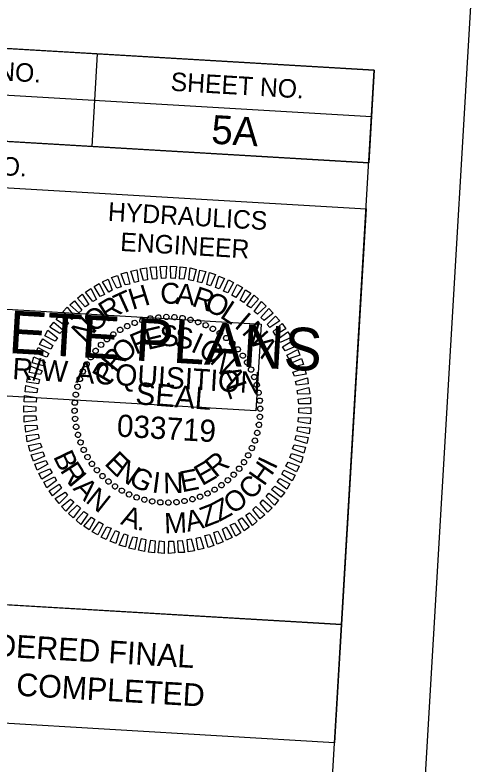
# Model space of a CAD drawing. Extents: x 2012145 to 2014096, y 444445 to 445643.
# Drawn here: x 2013972.6 to 2014096.1, y 445331.9 to 445534.5 of the extents above; entities that cross this region are included whole.
import ezdxf

# ---------------------------------------------------------------- set-up
doc = ezdxf.new("R2010")
doc.units = 0
for name, color, linetype in [('Sheet Data Field CELL', 7, 'Continuous'), ('Sheet Plan And Profile CELL', 7, 'Continuous'), ('Sheet Plot Border Outside CELL', 7, 'Continuous'), ('Sheet Professional Seal CELL', 7, 'Continuous'), ('Sheet Profile Grid Minor CELL', 7, 'Continuous'), ('Sheet Sticker Exception Certification CELL', 7, 'Continuous'), ('Sheet Sticker Incomplete CELL', 7, 'Continuous')]:
    doc.layers.add(name, color=color, linetype=linetype)

msp = doc.modelspace()

# ---------------------------------------------------------------- linework, layer by layer
at = {"layer": 'Sheet Plan And Profile CELL'}
for p, q in [((2013994.8, 445523.97), (2013993.33, 445499.01)), ((2013869.23, 445518.85), (2014068.93, 445507.08)), ((2013868.5, 445506.37), (2014068.2, 445494.6))]:
    msp.add_line(p, q, dxfattribs=at)
for points in [[(2014069.67, 445519.6), (2012572.27, 445607.87), (2012510.48, 444559.69), (2014007.88, 444471.42)], [(2013869.97, 445531.38), (2014069.67, 445519.6), (2014068.2, 445494.6), (2013868.5, 445506.37)], [(2013967.64, 445488), (2014067.46, 445482.12), (2014060.84, 445369.81), (2013961.02, 445375.7)]]:
    msp.add_lwpolyline(points, close=True, dxfattribs=at)
at = {"layer": 'Sheet Plot Border Outside CELL'}
msp.add_lwpolyline([(2012334.32, 444545.03), (2014031.37, 444445), (2014096.1, 445543.09), (2012399.05, 445643.13)], close=True, dxfattribs=at)
at = {"layer": 'Sheet Professional Seal CELL'}
for p, q in [((2014006.98, 445452.04), (2014006.98, 445452.04)), ((2014009.11, 445452.52), (2014009.11, 445452.52)), ((2014011.33, 445452.79), (2014011.33, 445452.79)), ((2014013.49, 445452.96), (2014013.49, 445452.96)), ((2014015.69, 445452.88), (2014015.69, 445452.88)), ((2014017.88, 445452.6), (2014017.88, 445452.6)), ((2014020.01, 445452.13), (2014020.01, 445452.13)), ((2014002.93, 445450.48), (2014002.93, 445450.48)), ((2014004.94, 445451.36), (2014004.94, 445451.36)), ((2014022.08, 445451.55), (2014022.08, 445451.55)), ((2014024.13, 445450.73), (2014024.13, 445450.73)), ((2013999.15, 445448.3), (2013999.15, 445448.3)), ((2014000.97, 445449.44), (2014000.97, 445449.44)), ((2014026.08, 445449.72), (2014026.08, 445449.72)), ((2014027.96, 445448.6), (2014027.96, 445448.6)), ((2013997.41, 445446.9), (2013997.41, 445446.9)), ((2014029.69, 445447.25), (2014029.69, 445447.25)), ((2014031.35, 445445.8), (2014031.35, 445445.8)), ((2013994.37, 445443.77), (2013994.37, 445443.77)), ((2013995.82, 445445.44), (2013995.82, 445445.44)), ((2014032.81, 445444.21), (2014032.81, 445444.21)), ((2013993.02, 445442.05), (2013993.02, 445442.05)), ((2014034.21, 445442.48), (2014034.21, 445442.48)), ((2013991.9, 445440.16), (2013991.9, 445440.16)), ((2014035.36, 445440.65), (2014035.36, 445440.65)), ((2013990.89, 445438.22), (2013990.89, 445438.22)), ((2014036.39, 445438.69), (2014036.39, 445438.69)), ((2013990.07, 445436.16), (2013990.07, 445436.16)), ((2014037.28, 445436.68), (2014037.28, 445436.68)), ((2013989.49, 445434.09), (2013989.49, 445434.09)), ((2014037.96, 445434.64), (2014037.96, 445434.64)), ((2013989.02, 445431.97), (2013989.02, 445431.97)), ((2014038.43, 445432.51), (2014038.43, 445432.51)), ((2013988.74, 445429.78), (2013988.74, 445429.78)), ((2014038.7, 445430.29), (2014038.7, 445430.29)), ((2013988.66, 445427.58), (2013988.66, 445427.58)), ((2014013.77, 445427.85), (2014013.77, 445427.85)), ((2014038.88, 445428.13), (2014038.88, 445428.13)), ((2014038.8, 445425.93), (2014038.8, 445425.93)), ((2013988.83, 445425.42), (2013988.83, 445425.42)), ((2014038.52, 445423.74), (2014038.52, 445423.74)), ((2013989.1, 445423.2), (2013989.1, 445423.2)), ((2014038.04, 445421.61), (2014038.04, 445421.61)), ((2013989.58, 445421.06), (2013989.58, 445421.06)), ((2014037.47, 445419.54), (2014037.47, 445419.54)), ((2013990.26, 445419.02), (2013990.26, 445419.02)), ((2014036.65, 445417.49), (2014036.65, 445417.49)), ((2013991.14, 445417.02), (2013991.14, 445417.02)), ((2014035.63, 445415.54), (2014035.63, 445415.54)), ((2013992.18, 445415.05), (2013992.18, 445415.05)), ((2014034.52, 445413.66), (2014034.52, 445413.66)), ((2013993.32, 445413.23), (2013993.32, 445413.23)), ((2013994.72, 445411.5), (2013994.72, 445411.5)), ((2014033.16, 445411.93), (2014033.16, 445411.93)), ((2013996.18, 445409.91), (2013996.18, 445409.91)), ((2014031.71, 445410.27), (2014031.71, 445410.27)), ((2013997.85, 445408.46), (2013997.85, 445408.46)), ((2014028.39, 445407.41), (2014028.39, 445407.41)), ((2014030.13, 445408.81), (2014030.13, 445408.81)), ((2013999.57, 445407.1), (2013999.57, 445407.1)), ((2014001.46, 445405.99), (2014001.46, 445405.99)), ((2014024.6, 445405.23), (2014024.6, 445405.23)), ((2014026.57, 445406.26), (2014026.57, 445406.26)), ((2014003.4, 445404.97), (2014003.4, 445404.97)), ((2014005.46, 445404.15), (2014005.46, 445404.15)), ((2014007.53, 445403.58), (2014007.53, 445403.58)), ((2014018.42, 445403.19), (2014018.42, 445403.19)), ((2014020.56, 445403.66), (2014020.56, 445403.66)), ((2014022.6, 445404.34), (2014022.6, 445404.34)), ((2014009.65, 445403.1), (2014009.65, 445403.1)), ((2014011.84, 445402.82), (2014011.84, 445402.82)), ((2014014.04, 445402.74), (2014014.04, 445402.74)), ((2014016.2, 445402.92), (2014016.2, 445402.92))]:
    msp.add_line(p, q, dxfattribs=at)
for points in [[(2014007.31, 445462.74), (2014006.45, 445465.95), (2014008.16, 445466.2), (2014008.37, 445462.93)], [(2014009.74, 445463.15), (2014009.13, 445466.39), (2014010.78, 445466.45), (2014010.94, 445463.23)], [(2014012.15, 445463.31), (2014011.79, 445466.54), (2014013.5, 445466.64), (2014013.36, 445463.39)], [(2014014.66, 445463.41), (2014014.6, 445466.67), (2014016.25, 445466.52), (2014015.86, 445463.29)], [(2014017.05, 445463.22), (2014017.25, 445466.47), (2014018.89, 445466.32), (2014018.25, 445463.1)], [(2014019.54, 445462.92), (2014019.93, 445466.16), (2014021.56, 445465.76), (2014020.73, 445462.65)], [(2014000.12, 445460.66), (2013998.69, 445463.55), (2014000.28, 445464.16), (2014001.25, 445461.05)], [(2014002.38, 445461.58), (2014001.26, 445464.55), (2014002.79, 445465.06), (2014003.65, 445461.81)], [(2014004.88, 445462.24), (2014003.9, 445465.3), (2014005.48, 445465.66), (2014005.94, 445462.52)], [(2014021.91, 445462.38), (2014022.55, 445465.55), (2014024.18, 445465.2), (2014023.1, 445462.16)], [(2014024.43, 445461.68), (2014025.12, 445464.9), (2014026.79, 445464.4), (2014025.46, 445461.37)], [(2014026.78, 445460.89), (2014027.72, 445463.94), (2014029.23, 445463.35), (2014027.81, 445460.48)], [(2013995.64, 445458.47), (2013993.94, 445461.13), (2013995.29, 445462), (2013996.77, 445459.01)], [(2013997.91, 445459.59), (2013996.22, 445462.4), (2013997.81, 445463.1), (2013998.89, 445460.13)], [(2014028.98, 445459.86), (2014030.31, 445462.94), (2014031.67, 445462.26), (2014030.11, 445459.45)], [(2013993.65, 445457.09), (2013991.65, 445459.61), (2013993.06, 445460.58), (2013994.64, 445457.68)], [(2014031.17, 445458.78), (2014032.59, 445461.65), (2014034.1, 445460.86), (2014032.23, 445458.17)], [(2014033.4, 445457.5), (2014034.91, 445460.26), (2014036.36, 445459.33), (2014034.31, 445456.84)], [(2013991.57, 445455.66), (2013989.5, 445457.98), (2013990.77, 445459.11), (2013992.55, 445456.3)], [(2014035.26, 445456.04), (2014037.18, 445458.83), (2014038.42, 445457.7), (2014036.33, 445455.37)], [(2013989.82, 445454.01), (2013987.39, 445456.2), (2013988.71, 445457.28), (2013990.66, 445454.76)], [(2014037.22, 445454.42), (2014039.23, 445457.06), (2014040.46, 445455.88), (2014038.13, 445453.66)], [(2013987.96, 445452.21), (2013985.48, 445454.31), (2013986.65, 445455.55), (2013988.71, 445453.07)], [(2014039.03, 445452.76), (2014041.23, 445455.23), (2014042.35, 445453.97), (2014039.93, 445451.95)], [(2013986.35, 445450.41), (2013983.75, 445452.26), (2013984.79, 445453.65), (2013987.05, 445451.32)], [(2014040.72, 445450.91), (2014043.01, 445453.13), (2014044.13, 445451.86), (2014041.42, 445450.06)], [(2013984.73, 445448.5), (2013982.03, 445450.16), (2013983.11, 445451.5), (2013985.58, 445449.35)], [(2014042.36, 445449.01), (2014044.79, 445451.12), (2014045.76, 445449.71), (2014043, 445447.97)], [(2013983.41, 445446.42), (2013980.64, 445447.84), (2013981.48, 445449.34), (2013984.06, 445447.33)], [(2014043.74, 445446.97), (2014046.31, 445448.92), (2014047.18, 445447.42), (2014044.29, 445445.99)], [(2013982.27, 445444.18), (2013979.25, 445445.51), (2013980.09, 445447.02), (2013982.84, 445445.25)], [(2014044.92, 445444.85), (2014047.68, 445446.59), (2014048.54, 445445.04), (2014045.56, 445443.81)], [(2013981.15, 445442.05), (2013978.1, 445443.13), (2013978.84, 445444.64), (2013981.76, 445443.06)], [(2014046.09, 445442.58), (2014048.99, 445444.16), (2014049.55, 445442.57), (2014046.63, 445441.59)], [(2013980.26, 445439.7), (2013977.2, 445440.53), (2013977.65, 445442.15), (2013980.72, 445440.72)], [(2014046.96, 445440.37), (2014049.99, 445441.7), (2014050.55, 445440.06), (2014047.4, 445439.24)], [(2013979.47, 445437.34), (2013976.4, 445437.92), (2013976.84, 445439.6), (2013979.93, 445438.36)], [(2014047.72, 445437.97), (2014050.84, 445439.09), (2014051.3, 445437.51), (2014048.16, 445436.89)], [(2013978.92, 445434.82), (2013975.74, 445435.3), (2013976.04, 445436.99), (2013979.24, 445436)], [(2014048.38, 445435.53), (2014051.64, 445436.49), (2014051.84, 445434.82), (2014048.67, 445434.46)], [(2013978.53, 445432.43), (2013975.29, 445432.73), (2013975.48, 445434.37), (2013978.7, 445433.63)], [(2014048.84, 445433.1), (2014052.04, 445433.86), (2014052.24, 445432.15), (2014049.07, 445432.03)], [(2013978.33, 445429.94), (2013975.08, 445429.98), (2013975.18, 445431.68), (2013978.4, 445431.14)], [(2014049.15, 445430.68), (2014052.43, 445431.18), (2014052.48, 445429.48), (2014049.27, 445429.47)], [(2013978.23, 445427.44), (2013974.96, 445427.24), (2013974.96, 445428.94), (2013978.2, 445428.65)], [(2014049.3, 445428.26), (2014052.57, 445428.47), (2014052.57, 445426.77), (2014049.33, 445427.06)], [(2013978.39, 445425.03), (2013975.1, 445424.52), (2013975.05, 445426.23), (2013978.26, 445426.24)], [(2014049.21, 445425.76), (2014052.46, 445425.72), (2014052.36, 445424.03), (2014049.14, 445424.57)], [(2013978.7, 445422.61), (2013975.5, 445421.84), (2013975.3, 445423.56), (2013978.46, 445423.67)], [(2014049.01, 445423.27), (2014052.25, 445422.98), (2014052.05, 445421.34), (2014048.84, 445422.08)], [(2013979.16, 445420.18), (2013975.89, 445419.22), (2013975.69, 445420.88), (2013978.87, 445421.25)], [(2014048.62, 445420.89), (2014051.8, 445420.4), (2014051.5, 445418.72), (2014048.3, 445419.71)], [(2013979.81, 445417.73), (2013976.69, 445416.62), (2013976.23, 445418.19), (2013979.38, 445418.81)], [(2014048.07, 445418.37), (2014051.14, 445417.79), (2014050.69, 445416.11), (2014047.61, 445417.34)], [(2013980.57, 445415.33), (2013977.54, 445414.01), (2013976.99, 445415.65), (2013980.14, 445416.46)], [(2014047.28, 445416.01), (2014050.34, 445415.18), (2014049.89, 445413.55), (2014046.82, 445414.99)], [(2013981.45, 445413.13), (2013978.55, 445411.55), (2013977.99, 445413.13), (2013980.9, 445414.11)], [(2014046.39, 445413.66), (2014049.43, 445412.58), (2014048.69, 445411.07), (2014045.78, 445412.64)], [(2013982.61, 445410.86), (2013979.86, 445409.12), (2013979, 445410.67), (2013981.97, 445411.9)], [(2014045.26, 445411.52), (2014048.29, 445410.19), (2014047.45, 445408.69), (2014044.7, 445410.45)], [(2013983.79, 445408.73), (2013981.22, 445406.78), (2013980.36, 445408.28), (2013983.25, 445409.72)], [(2014044.13, 445409.28), (2014046.9, 445407.87), (2014046.06, 445406.37), (2014043.47, 445408.37)], [(2013985.17, 445406.7), (2013982.74, 445404.59), (2013981.78, 445406), (2013984.53, 445407.74)], [(2013986.81, 445404.8), (2013984.53, 445402.58), (2013983.4, 445403.85), (2013986.11, 445405.64)], [(2014041.19, 445405.3), (2014043.78, 445403.44), (2014042.75, 445402.05), (2014040.48, 445404.39)], [(2014042.8, 445407.21), (2014045.51, 445405.55), (2014044.43, 445404.21), (2014041.95, 445406.36)], [(2013988.51, 445402.95), (2013986.31, 445400.47), (2013985.18, 445401.74), (2013987.6, 445403.75)], [(2014039.58, 445403.49), (2014042.06, 445401.39), (2014040.88, 445400.16), (2014038.83, 445402.63)], [(2013990.31, 445401.29), (2013988.31, 445398.65), (2013987.07, 445399.83), (2013989.41, 445402.04)], [(2014037.72, 445401.7), (2014040.14, 445399.5), (2014038.83, 445398.43), (2014036.87, 445400.95)], [(2013992.27, 445399.67), (2013990.35, 445396.88), (2013989.12, 445398), (2013991.21, 445400.33)], [(2014035.97, 445400.05), (2014038.04, 445397.72), (2014036.77, 445396.6), (2014034.98, 445399.41)], [(2013994.14, 445398.21), (2013992.62, 445395.44), (2013991.18, 445396.38), (2013993.23, 445398.86)], [(2013996.37, 445396.92), (2013994.95, 445394.05), (2013993.44, 445394.84), (2013995.3, 445397.54)], [(2014031.9, 445397.23), (2014033.59, 445394.58), (2014032.24, 445393.71), (2014030.76, 445396.7)], [(2014033.88, 445398.62), (2014035.89, 445396.1), (2014034.48, 445395.13), (2014032.9, 445398.03)], [(2013998.56, 445395.84), (2013997.22, 445392.77), (2013995.86, 445393.45), (2013997.43, 445396.26)], [(2014000.75, 445394.81), (2013999.82, 445391.76), (2013998.3, 445392.35), (2013999.72, 445395.22)], [(2014029.63, 445396.11), (2014031.32, 445393.31), (2014029.72, 445392.6), (2014028.64, 445395.57)], [(2014003.11, 445394.02), (2014002.42, 445390.81), (2014000.74, 445391.31), (2014002.07, 445394.33)], [(2014005.62, 445393.32), (2014004.98, 445390.15), (2014003.35, 445390.5), (2014004.43, 445393.54)], [(2014007.99, 445392.78), (2014007.6, 445389.55), (2014005.97, 445389.95), (2014006.81, 445393.05)], [(2014022.66, 445393.47), (2014023.63, 445390.41), (2014022.06, 445390.05), (2014021.59, 445393.18)], [(2014025.15, 445394.12), (2014026.28, 445391.15), (2014024.75, 445390.64), (2014023.89, 445393.9)], [(2014027.41, 445395.04), (2014028.84, 445392.15), (2014027.25, 445391.55), (2014026.29, 445394.66)], [(2014010.48, 445392.48), (2014010.29, 445389.24), (2014008.65, 445389.39), (2014009.29, 445392.61)], [(2014012.87, 445392.29), (2014012.93, 445389.03), (2014011.29, 445389.18), (2014011.68, 445392.41)], [(2014015.38, 445392.4), (2014015.74, 445389.17), (2014014.04, 445389.07), (2014014.18, 445392.32)], [(2014017.8, 445392.55), (2014018.41, 445389.31), (2014016.75, 445389.26), (2014016.59, 445392.48)], [(2014020.23, 445392.96), (2014021.09, 445389.76), (2014019.37, 445389.51), (2014019.16, 445392.77)]]:
    msp.add_lwpolyline(points, close=True, dxfattribs=at)
for centre, major_axis in [((2014004.93, 445451.33), (-0.254, 0.674)), ((2014007.01, 445452.01), (-0.194, 0.693)), ((2014009.14, 445452.5), (-0.133, 0.708)), ((2014011.31, 445452.81), (-0.071, 0.717)), ((2014013.49, 445452.93), (-0.008, 0.72)), ((2014015.68, 445452.86), (0.055, 0.718)), ((2014017.85, 445452.6), (0.117, 0.71)), ((2014019.99, 445452.15), (0.179, 0.697)), ((2014022.09, 445451.51), (0.239, 0.679)), ((2014000.99, 445449.43), (-0.367, 0.62)), ((2014002.92, 445450.47), (-0.311, 0.649)), ((2014024.12, 445450.7), (0.297, 0.656)), ((2014026.07, 445449.71), (0.353, 0.627)), ((2013999.16, 445448.24), (-0.419, 0.585)), ((2014027.93, 445448.55), (0.407, 0.594)), ((2014029.68, 445447.24), (0.457, 0.557)), ((2013995.84, 445445.39), (-0.515, 0.504)), ((2013997.44, 445446.89), (-0.469, 0.546)), ((2014031.31, 445445.78), (0.504, 0.515)), ((2013994.38, 445443.76), (-0.557, 0.457)), ((2014032.8, 445444.18), (0.546, 0.469)), ((2013993.07, 445442.01), (-0.594, 0.407)), ((2014034.15, 445442.46), (0.585, 0.419)), ((2013991.91, 445440.15), (-0.627, 0.353)), ((2014035.35, 445440.63), (0.62, 0.367)), ((2013990.92, 445438.2), (-0.656, 0.297)), ((2014036.38, 445438.7), (0.649, 0.311)), ((2013990.11, 445436.17), (-0.679, 0.239)), ((2014037.24, 445436.69), (0.674, 0.254)), ((2013989.47, 445434.08), (-0.697, 0.179)), ((2014037.92, 445434.61), (0.693, 0.194)), ((2013989.02, 445431.94), (-0.71, 0.117)), ((2014038.42, 445432.48), (0.708, 0.133)), ((2013988.76, 445429.77), (-0.718, 0.055)), ((2014038.73, 445430.31), (0.717, 0.071)), ((2013988.69, 445427.58), (-0.72, -0.008)), ((2014038.85, 445428.13), (0.72, 0.008)), ((2013988.81, 445425.39), (-0.717, -0.071)), ((2014038.77, 445425.94), (0.718, -0.055)), ((2013989.12, 445423.23), (-0.708, -0.133)), ((2014038.51, 445423.77), (0.71, -0.117)), ((2013989.61, 445421.1), (-0.693, -0.194)), ((2014038.06, 445421.63), (0.697, -0.179)), ((2013990.3, 445419.02), (-0.674, -0.254)), ((2014037.43, 445419.53), (0.679, -0.239)), ((2013991.15, 445417.01), (-0.649, -0.311)), ((2014036.61, 445417.5), (0.656, -0.297)), ((2013992.19, 445415.08), (-0.62, -0.367)), ((2014035.62, 445415.55), (0.627, -0.353)), ((2013993.38, 445413.24), (-0.585, -0.419)), ((2014034.47, 445413.69), (0.594, -0.407)), ((2013994.73, 445411.52), (-0.546, -0.469)), ((2014033.16, 445411.94), (0.557, -0.457)), ((2013996.23, 445409.93), (-0.504, -0.515)), ((2013997.86, 445408.47), (-0.457, -0.557)), ((2014030.1, 445408.82), (0.469, -0.546)), ((2014031.69, 445410.31), (0.515, -0.504)), ((2013999.61, 445407.15), (-0.407, -0.594)), ((2014028.38, 445407.47), (0.419, -0.585)), ((2014001.47, 445406), (-0.353, -0.627)), ((2014003.42, 445405.01), (-0.297, -0.656)), ((2014022.6, 445404.38), (0.254, -0.674)), ((2014024.61, 445405.24), (0.311, -0.649)), ((2014026.54, 445406.27), (0.367, -0.62)), ((2014005.45, 445404.19), (-0.239, -0.679)), ((2014007.54, 445403.56), (-0.179, -0.697)), ((2014009.68, 445403.11), (-0.117, -0.71)), ((2014011.86, 445402.85), (-0.055, -0.718)), ((2014014.04, 445402.77), (0.008, -0.72)), ((2014016.23, 445402.89), (0.071, -0.717)), ((2014018.39, 445403.2), (0.133, -0.708)), ((2014020.52, 445403.7), (0.194, -0.693))]:
    msp.add_ellipse(centre, major_axis=major_axis, ratio=0.999708, dxfattribs=at)
at = {"layer": 'Sheet Sticker Exception Certification CELL'}
for p, q in [((2013861.14, 445381.6), (2014060.84, 445369.83)), ((2014060.84, 445369.81), (2014058.96, 445337.89)), ((2014058.96, 445337.91), (2013859.26, 445349.68))]:
    msp.add_line(p, q, dxfattribs=at)
at = {"layer": 'Sheet Sticker Incomplete CELL'}
msp.add_lwpolyline([(2013890.95, 445436.18), (2013892.34, 445459.64), (2014039.08, 445450.99), (2014037.7, 445427.53)], close=True, dxfattribs=at)

# ---------------------------------------------------------------- texts
at = {"layer": 'Sheet Data Field CELL'}
msp.add_text('5A', height=7.75, rotation=356.6264, dxfattribs=at).set_placement((2014025.5, 445499.77))
at = {"layer": 'Sheet Plan And Profile CELL'}
for s, height, p in [('PROJECT REFERENCE NO.', 5.0001, (2013891.62, 445521.39)), ('SHEET NO.', 5, (2014014.55, 445514.04)), ('R/W SHEET NO.', 5.0001, (2013924.86, 445493.83)), ('HYDRAULICS', 5, (2013997.6, 445478.93)), ('ENGINEER', 5, (2014000.93, 445470.77))]:
    msp.add_text(s, height=height, rotation=356.6264, dxfattribs=at).set_placement(p)
at = {"layer": 'Sheet Professional Seal CELL'}
for s, height, rotation, p in [('C', 5.64, 2.8463, (2014011.99, 445456.36)), ('T', 5.64, 24.4462, (2014000.95, 445453.35)), ('H', 5.64, 17.2459, (2014004.29, 445454.81)), ('A', 5.64, 355.6467, (2014015.95, 445456.42)), ('R', 5.64, 341.2475, (2014020.13, 445455.98)), ('R', 5.64, 31.6469, (2013997.42, 445451.36)), ('O', 5.64, 334.0476, (2014023.43, 445455.03)), ('L', 5.64, 326.8473, (2014027.72, 445452.93)), ('O', 5.64, 38.8482, (2013993.8, 445448.46)), ('I', 5.64, 319.6466, (2014031.62, 445450.29)), ('N', 5.64, 46.0499, (2013991.33, 445445.7)), ('N', 5.64, 312.4453, (2014033.67, 445448.62)), ('E', 5.64, 13.2375, (2014008.46, 445443.99)), ('S', 5.64, 3.882, (2014011.96, 445444.84)), ('S', 5.64, 354.5268, (2014015.56, 445444.68)), ('F', 5.64, 22.5935, (2014005.18, 445442.68)), ('I', 5.64, 335.816, (2014019.81, 445443.72)), ('O', 5.64, 41.3077, (2014001.71, 445439.93)), ('O', 5.64, 326.4599, (2014021.77, 445442.91)), ('A', 5.64, 305.2436, (2014036.45, 445445.5)), ('R', 5.64, 50.6661, (2013999.82, 445437.59)), ('N', 5.64, 317.103, (2014024.99, 445440.71)), ('P', 5.64, 60.0253, (2013998.03, 445434.49)), ('A', 5.64, 298.3867, (2014027.69, 445437.95)), ('L', 5.64, 289.0273, (2014029.43, 445434.39)), ('SEAL', 5.998, 355.6264, (2014004.99, 445429.37)), ('E', 5.64, 314.9033, (2013996.48, 445413.2)), ('R', 5.64, 39.1078, (2014026.8, 445409.3)), ('N', 5.64, 324.2604, (2013999.31, 445410.32)), ('E', 5.64, 29.7505, (2014023.12, 445407.17)), ('G', 5.64, 333.6167, (2014002.97, 445407.85)), ('E', 5.64, 11.0382, (2014017.71, 445405.53)), ('I', 5.64, 352.3276, (2014009.4, 445405.57)), ('N', 5.64, 1.6828, (2014012.73, 445405.22))]:
    msp.add_text(s, height=height, rotation=rotation, dxfattribs=at).set_placement(p)
at = {"layer": 'Sheet Profile Grid Minor CELL'}
for s, height, rotation, p in [('033719', 5.998, 356.6264, (2014000, 445420.64)), ('B', 5.5, 295.7793, (2013982.82, 445415.21)), ('R', 5.5, 302.9061, (2013984.63, 445411.47)), ('H', 5.5, 54.9743, (2014039.9, 445407)), ('I', 5.5, 64.2191, (2014042.91, 445411.47)), ('I', 5.5, 309.8326, (2013986.82, 445408.08)), ('C', 5.5, 46.1015, (2014036.37, 445403.22)), ('A', 5.5, 313.353, (2013988.08, 445406.46)), ('N', 5.5, 321.5388, (2013991.39, 445403.02)), ('O', 5.5, 35.397, (2014031.4, 445399.45)), ('Z', 5.5, 28.2703, (2014027.74, 445397.49)), ('A', 5.5, 340.9157, (2014000.9, 445397)), ('Z', 5.5, 21.1435, (2014023.87, 445395.99)), ('M', 5.5, 2.2818, (2014013.02, 445394.43)), ('A', 5.5, 12.9577, (2014019.23, 445394.87)), ('.', 5.5, 349.1015, (2014005.42, 445395.48))]:
    msp.add_text(s, height=height, rotation=rotation, dxfattribs=at).set_placement(p)
at = {"layer": 'Sheet Sticker Exception Certification CELL'}
for s, p in [('DOCUMENT NOT CONSIDERED FINAL', (2013871.92, 445366.87)), ('UNLESS ALL SIGNATURES COMPLETED', (2013865.59, 445356.96))]:
    msp.add_text(s, height=6.124, rotation=356.6264, dxfattribs=at).set_placement(p)
at = {"layer": 'Sheet Sticker Incomplete CELL'}
for s, height, p in [('INCOMPLETE PLANS', 11.52, (2013900.58, 445447.33)), ('DO NOT USE FOR R/W ACQUISITION', 5.76, (2013903.41, 445440.2))]:
    msp.add_text(s, height=height, rotation=356.6264, dxfattribs=at).set_placement(p)

doc.saveas('drawing.dxf')
